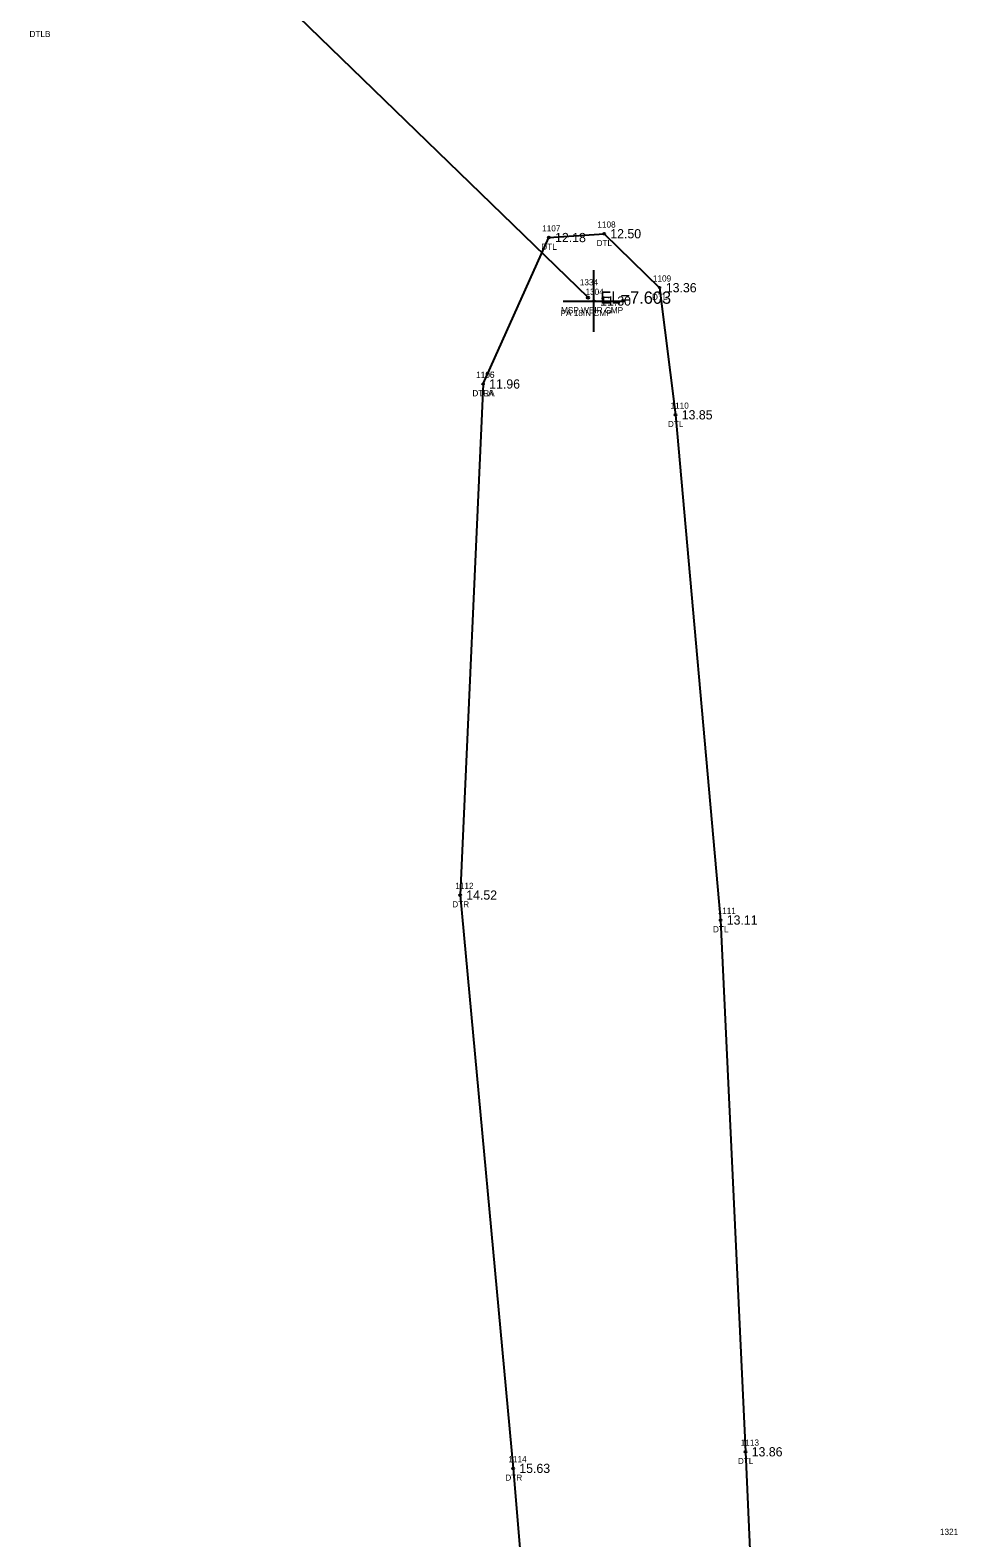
# Model space of a CAD drawing. Extents: x 2072307 to 2072993, y 127574 to 129736.
# Drawn here: x 2072323.7 to 2072474.7, y 127825.4 to 128070.8 of the extents above; entities that cross this region are included whole.
import ezdxf

# ---------------------------------------------------------------- set-up
doc = ezdxf.new("R2010")
doc.units = 0
for name, color, linetype in [('RD_EX_DR_Pipe', 7, 'Continuous'), ('RD_EX_DR_Pipe_txCode', 7, 'Continuous'), ('RD_EX_H2O', 7, 'Continuous'), ('RD_EX_H2O_txCode', 7, 'Continuous'), ('RD_EX_Misc', 7, 'Continuous'), ('RD_EX_Misc_txCode', 7, 'Continuous'), ('RD_EX_TX_H2O_ELEV', 7, 'Continuous'), ('RD_EX_TX_Misc_ELEV', 7, 'Continuous'), ('RD_SMD_Locator', 7, 'Continuous'), ('RD_TX_Pipe_ElevEX', 7, 'Continuous')]:
    doc.layers.add(name, color=color, linetype=linetype)

msp = doc.modelspace()

# ---------------------------------------------------------------- linework, layer by layer
at = {"layer": 'RD_EX_DR_Pipe'}
msp.add_line((2072414.52, 128027.27), (2072341.02, 128098.6), dxfattribs=at)
at = {"layer": 'RD_EX_H2O'}
for points in [[(2072397.43, 128013.21), (2072408.15, 128037.05), (2072417.14, 128037.67), (2072426.18, 128028.89), (2072428.77, 128008.19), (2072436.1, 127925.95), (2072440.16, 127839.38), (2072444.26, 127746.21), (2072439.54, 127661.97), (2072428.72, 127652.16), (2072418.72, 127654.12), (2072416.39, 127665.39)], [(2072397.43, 128013.21), (2072393.69, 127930.01), (2072402.33, 127836.68), (2072410.62, 127737.08), (2072416.39, 127665.39)]]:
    msp.add_lwpolyline(points, dxfattribs=at)
at = {"layer": 'RD_EX_Misc'}
for p, q in [((2072415.49, 128021.72), (2072415.49, 128031.72)), ((2072410.49, 128026.72), (2072420.49, 128026.72))]:
    msp.add_line(p, q, dxfattribs=at)
at = {"layer": 'RD_SMD_Locator'}
for centre, radius in [((2072408.15, 128037.05), 0.15), ((2072417.14, 128037.67), 0.15), ((2072426.18, 128028.89), 0.15), ((2072414.52, 128027.27), 0.2), ((2072415.49, 128026.72), 0.15), ((2072397.43, 128013.21), 0.15), ((2072397.43, 128013.21), 0.15), ((2072428.77, 128008.19), 0.15), ((2072393.69, 127930.01), 0.15), ((2072436.1, 127925.95), 0.15), ((2072440.16, 127839.38), 0.15), ((2072402.33, 127836.68), 0.15)]:
    msp.add_circle(centre, radius, dxfattribs=at)

# ---------------------------------------------------------------- texts
at = {"layer": 'RD_EX_DR_Pipe_txCode'}
for s, p in [('1334', (2072413.18, 128029.27)), ('PA 18IN CMP', (2072410.04, 128024.27)), ('1321', (2072471.81, 127825.86))]:
    msp.add_text(s, height=1, dxfattribs=at).set_placement(p)
at = {"layer": 'RD_EX_H2O_txCode'}
for s, p in [('DTLB', (2072323.59, 128069.69)), ('1107', (2072407.05, 128038.05)), ('1108', (2072416.04, 128038.67)), ('DTL', (2072415.9, 128035.67)), ('DTL', (2072406.91, 128035.05)), ('1109', (2072425.08, 128029.89)), ('DTL', (2072424.94, 128026.89)), ('1106', (2072396.3, 128014.21)), ('1105', (2072396.33, 128014.21)), ('DTRA', (2072395.67, 128011.21)), ('DTLA', (2072395.7, 128011.21)), ('1110', (2072427.95, 128009.19)), ('DTL', (2072427.52, 128006.19)), ('1112', (2072392.91, 127931.01)), ('DTR', (2072392.42, 127928.01)), ('1111', (2072435.61, 127926.95)), ('DTL', (2072434.86, 127923.95)), ('1113', (2072439.38, 127840.38)), ('1114', (2072401.55, 127837.68)), ('DTL', (2072438.91, 127837.38)), ('DTR', (2072401.06, 127834.68))]:
    msp.add_text(s, height=1, dxfattribs=at).set_placement(p)
at = {"layer": 'RD_EX_Misc_txCode'}
for s, p in [('1304', (2072414.11, 128027.72)), ('MSP WEIR CMP', (2072410.13, 128024.72))]:
    msp.add_text(s, height=1, dxfattribs=at).set_placement(p)
at = {"layer": 'RD_EX_TX_H2O_ELEV'}
for s, p in [('12.18', (2072409.15, 128036.3)), ('12.50', (2072418.14, 128036.92)), ('13.36', (2072427.18, 128028.14)), ('11.96', (2072398.43, 128012.46)), ('11.96', (2072398.43, 128012.46)), ('13.85', (2072429.77, 128007.44)), ('14.52', (2072394.69, 127929.26)), ('13.11', (2072437.1, 127925.2)), ('13.86', (2072441.16, 127838.63)), ('15.63', (2072403.33, 127835.93))]:
    msp.add_text(s, height=1.5, dxfattribs=at).set_placement(p)
at = {"layer": 'RD_EX_TX_Misc_ELEV'}
msp.add_text('11.30', height=1.5, dxfattribs=at).set_placement((2072416.49, 128025.97))
at = {"layer": 'RD_TX_Pipe_ElevEX'}
msp.add_text('EL=7.603', height=2, dxfattribs=at).set_placement((2072416.52, 128026.27))

doc.saveas('drawing.dxf')
